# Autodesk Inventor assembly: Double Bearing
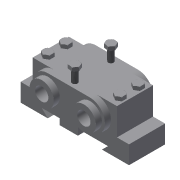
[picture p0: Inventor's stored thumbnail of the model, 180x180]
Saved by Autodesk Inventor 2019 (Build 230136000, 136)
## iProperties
Shininess: 64.0
Length Units: 11269
Angle Units: 11279
Time Units: 11290
Mass Units: 11283
Length Display Precision: 3
Angle Display Precision: 2
Created: 2002-02
Part Number: Double Bearing
Document SubType Name: Assembly
Designer: ***
Density: 0.0
Volumn: 0.0
Area: 0.0
PropertySet Name: Model Information
Control State: 0
Master: False
Checked Out: False
Author: ***
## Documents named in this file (5)
- E:\_Deepak\Inventor\Projects\Autodesk Inventor_2019_Project\Resources\Inventor_2018_tut\c10_Inv_2019_tut\c10_Inv_tut_2019\c10_tut03_inv\Double Bearing Assembly\Double Bearing.iam
- E:\_Deepak\Inventor\Projects\Autodesk Inventor_2019_Project\Resources\Inventor_2018_tut\c10_Inv_2019_tut\c10_Inv_tut_2019\c10_tut03_inv\Double Bearing Assembly\Base.ipt
- E:\_Deepak\Inventor\Projects\Autodesk Inventor_2019_Project\Resources\Inventor_2018_tut\c10_Inv_2019_tut\c10_Inv_tut_2019\c10_tut03_inv\Double Bearing Assembly\Cap.ipt
- E:\_Deepak\Inventor\Projects\Autodesk Inventor_2019_Project\Resources\Inventor_2018_tut\c10_Inv_2019_tut\c10_Inv_tut_2019\c10_tut03_inv\Double Bearing Assembly\Bushing.ipt
- E:\_Deepak\Inventor\Projects\Autodesk Inventor_2019_Project\Resources\Inventor_2018_tut\c10_Inv_2019_tut\c10_Inv_tut_2019\c10_tut03_inv\Double Bearing Assembly\Bolt.ipt
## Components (10 placed, 4 different names)
1. Base:1 — Insert:1, Insert:2
2. Cap:1 — Insert:1, Insert:2, Insert:3, Insert:4, Insert:5, Insert:6
3. Bushing:1 — Insert:3
4. Bushing:2 — Insert:4
5. Bolt:1 — Insert:5
6. Bolt:6
7. Bolt:7
8. Bolt:8
9. Bolt:5 — Insert:6
10. Bolt:9
## Component patterns: Component Pattern 1 (4 elements), Component Pattern 2 (2 elements)
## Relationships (6: Insert 6)
- Insert:1: Base:1 ↔ Cap:1
- Insert:2: Base:1 ↔ Cap:1
- Insert:3: Cap:1 ↔ Bushing:1
- Insert:4: Cap:1 ↔ Bushing:2
- Insert:5: Cap:1 ↔ Bolt:1
- Insert:6: Cap:1 ↔ Bolt:5
